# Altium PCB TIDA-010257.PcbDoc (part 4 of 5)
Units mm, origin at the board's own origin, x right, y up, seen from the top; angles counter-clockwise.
Board outline 250 x 270 mm, 2 copper layers (Top Layer, Bottom Layer), stack 1.575 mm thick; 458 components, 220 nets, 1154 pads, 1226 vias.
Unrouted connection lines stored in the file: 314.
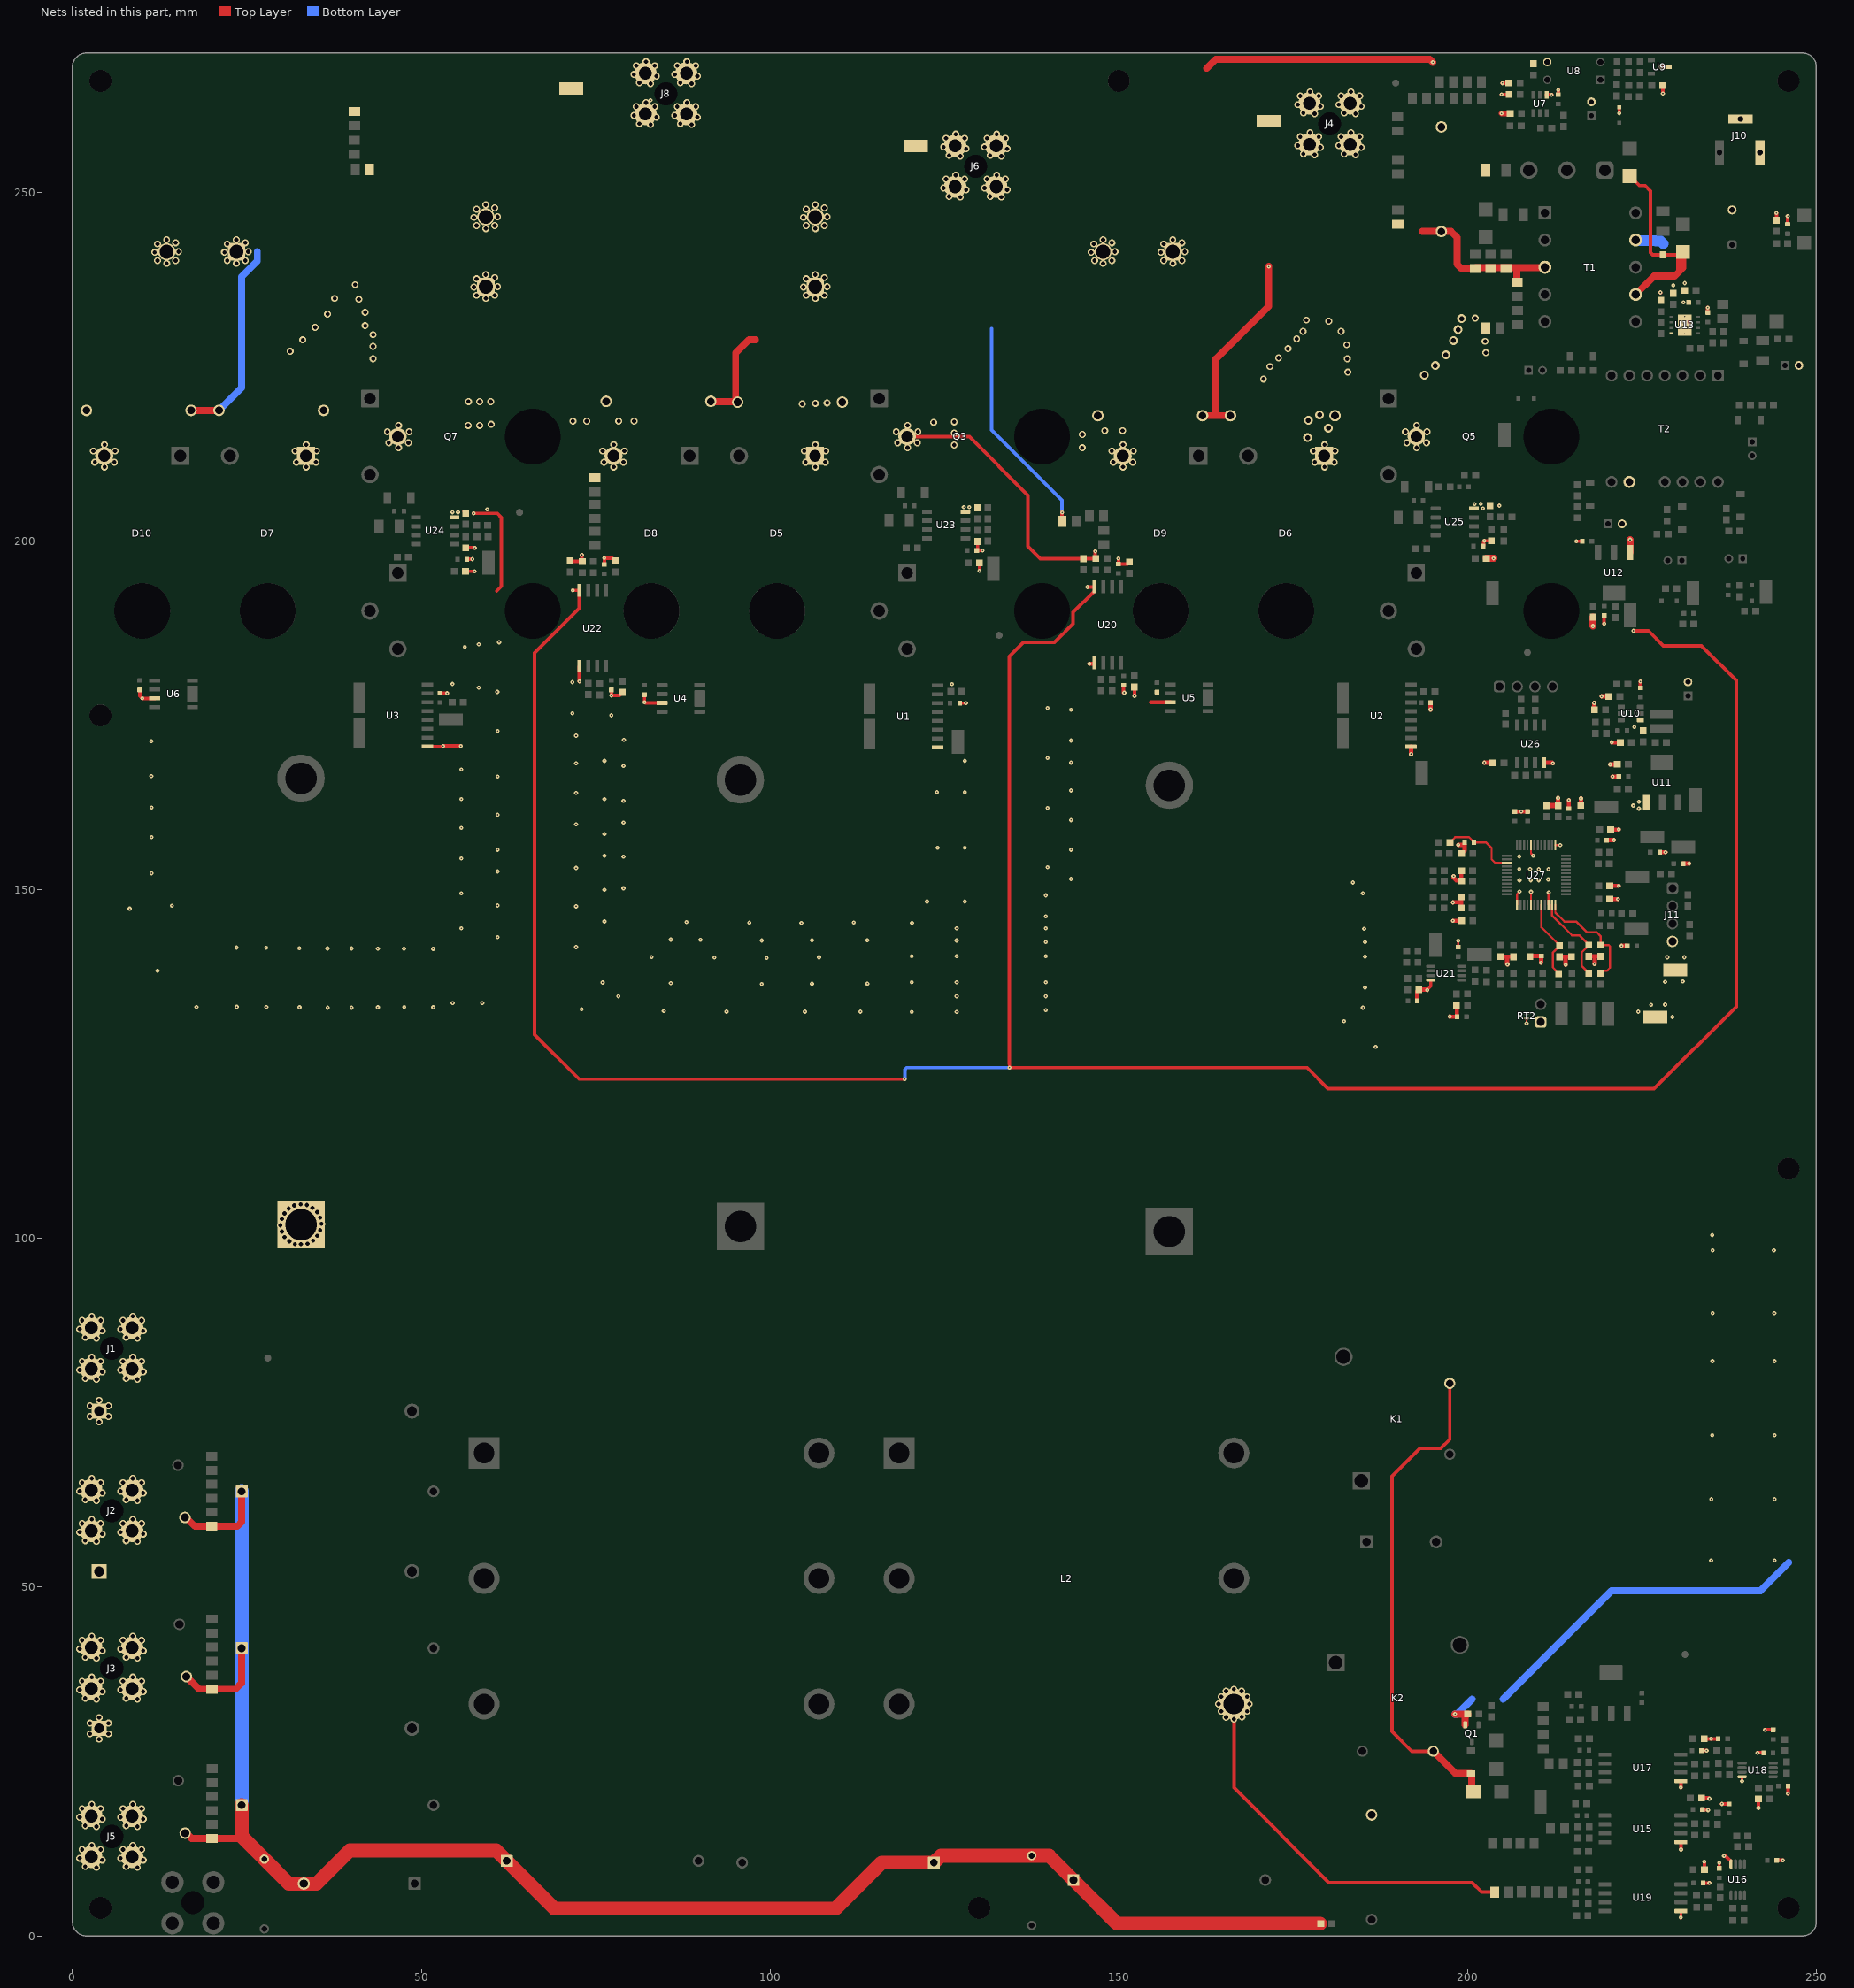
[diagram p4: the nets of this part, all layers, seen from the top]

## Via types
v1: diameter 1, hole 0.6, Top Layer to Bottom Layer, 760 vias
v2: diameter 0.6, hole 0.2, Top Layer to Bottom Layer, 452 vias
v3: diameter 1.27, hole 0.711, Top Layer to Bottom Layer, 10 vias
v4: diameter 0.5, hole 0.2, Top Layer to Bottom Layer, 4 vias

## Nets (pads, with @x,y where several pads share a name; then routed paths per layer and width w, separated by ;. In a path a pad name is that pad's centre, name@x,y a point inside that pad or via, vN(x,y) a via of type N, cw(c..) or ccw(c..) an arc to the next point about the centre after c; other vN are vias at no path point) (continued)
V_C: L2.6 L7.1 R104.1 | length 57.5
  Top Layer w0.2: L7.1@29.7,104.9 30.6,104.9 L7.1@30.7,104.8 ; L7.1@29.75,99.2 29.9,99.2 L7.1@30.4,98.7
  Top Layer w0.5: L2.6@166.5,33.25 v1(166.5,31.1) 166.5,21.25 180.113,7.637 200.65,7.637 202.015,6.271 R104.1@203.891,6.271
  other v1: 165.4,31.35 167.65,31.4 164.7,32.2 168.4,32.2 164.3,33.25 168.7,33.25 164.7,34.3 168.4,34.3 165.4,35.1 167.6,35.1 166.5,35.375 31.9,99.2 32.75,99.2 33.7,99.265 31.1,99.6 34.5,99.7 30.4,100.2 35.1,100.4 30,101 35.5,101.2 29.8,101.9 35.7,102.1 30,102.8 35.5,103 30.4,103.6 35.1,103.8 31,104.3 34.4,104.4 31.8,104.735 33.6,104.8 32.7,104.9
V_L1: F1.1 J1.1
  other v1: 3.83,73.7 2.52,74.468 5.16,74.468 2.52,76 5.16,76 3.83,76.8 3.43,79.817 9.3,79.817 1.83,79.93 7.7,79.93 4.267,80.88 10.137,80.88 1.03,81.13 6.9,81.13 1.38,82.38 4.03,82.38 7.25,82.38 9.9,82.38 2.77,82.967 8.64,82.967 3.43,85.687 9.3,85.687 1.83,85.8 7.7,85.8 4.267,86.75 10.137,86.75 1.03,87 6.9,87 1.38,88.25 4.03,88.25 7.25,88.25 9.9,88.25 2.77,88.837 8.64,88.837
V_L2: F2.1 J2.1
  other v1: 3.43,56.567 9.3,56.567 1.83,56.68 7.7,56.68 4.267,57.63 10.137,57.63 1.03,57.88 6.9,57.88 1.38,59.13 4.03,59.13 7.25,59.13 9.9,59.13 2.77,59.717 8.64,59.717 3.43,62.437 9.3,62.437 1.83,62.55 7.7,62.55 4.267,63.5 10.137,63.5 1.03,63.75 6.9,63.75 1.38,65 4.03,65 7.25,65 9.9,65 2.77,65.587 8.64,65.587
V_L3: F3.1 J3.1
  other v1: 3.83,28.2 2.52,28.968 5.16,28.968 2.52,30.5 5.16,30.5 3.83,31.3 3.43,33.952 9.3,33.952 1.83,34.065 7.7,34.065 4.267,35.015 10.137,35.015 1.03,35.265 6.9,35.265 1.38,36.515 4.03,36.515 7.25,36.515 9.9,36.515 2.77,37.103 8.64,37.103 3.43,39.822 9.3,39.822 1.83,39.935 7.7,39.935 4.267,40.885 10.137,40.885 1.03,41.135 6.9,41.135 1.38,42.385 4.03,42.385 7.25,42.385 9.9,42.385 2.77,42.973 8.64,42.973
V_Relay: D2.1 D4.1 K1.4 K2.4 | length 71.5
  Top Layer w0.5: K2.4@195.08,26.479 192,26.479 189.151,29.328 189.151,65.901 193.155,69.905 196.155,69.905 197.45,71.2 K1.4@197.45,79.22
  Top Layer w1: K2.4@195.08,26.479 198.264,23.294 D2.1@200.499,23.294 ; D2.1@200.609,23.252 200.609,20.951 D4.1@200.831,20.729
VA_AD: C85.2 R85.1 U27.20 | length 11.7
  Top Layer w0.3: U27.20@210.588,147.877 210.588,144.627 213.198,142.017 C85.2@213.198,141.992 213.198,141.967 212.449,141.218 212.44,141.218 212.213,140.991 212.213,138.896 213.088,138.021 R85.1@213.088,137.996
Vaux: C34.2 D11.2 D13.2 T1.7 | length 29.7
  Top Layer w0.5: D13.2@223.25,252.36 224.619,250.991 225.458,250.991 226.229,250.22 226.229,241.361 226.522,241.068 C34.2@228.058,241.068 D11.2@230.461,241.068
  Top Layer w1: T1.7@224.098,235.38 226.718,238 229.673,238 230.872,239.199 D11.2@230.872,241.48 ; 230.372,239.086 230.372,240.98 D11.2@230.461,241.068
VB_AD: C95.2 R98.1 U27.23 | length 13.6
  Top Layer w0.3: U27.23@212.088,147.877 212.088,146.362 214.963,143.487 216.007,143.487 217.391,142.103 C95.2@217.391,142.078 217.391,142.053 216.388,141.051 216.388,139.067 217.391,138.065 R98.1@217.391,138.04 R98.1@217.327,138.103
VBUSM: C10.2 C14.2 C15.2 C16.2 C18.1 C19.2 C22.1 C23.2 C24.1 C25.1 C27.1 C53.2 C54.2 C55.1 C56.1 C106.2 C107.1 C115.2 C116.1 J6.1 Q3.2 Q5.2 Q7.2 R17.1 R19.2 R117.2 R120.2 R128.1 R131.1 T2.9 TP4.1 U12.1 U20.4 U22.4 | length 516.7
  Top Layer w0.5: R131.1@71.315,197.167 71.37,197.112 73.019,197.112 R128.1@73.028,197.103 ; v2(71.736,192.946) 71.81,192.946 71.815,192.95 U22.4@72.66,192.95 72.66,190.367 66.25,183.957 66.25,129.25 72.65,122.85 v2(119.3,122.85) ; v2(73.028,198.038) R128.1@73.028,197.103 ; R128.1@73.074,197.057 R128.1@73.028,197.103 ; v2(76.236,197.57) v2@76.25,197.57 ; C116.1@76.25,196.675 v2@76.25,197.57 ; C115.2@77.815,197.166 77.815,197.191 77.59,197.416 77.565,197.416 77.412,197.57 v2@76.25,197.57 ; Q3.2@119.648,215 128.567,215 136.99,206.578 136.99,199.257 138.756,197.491 146.685,197.491 R117.2@146.7,197.506 146.636,197.57 v2(146.636,198.548) ; v2(145.499,193.42) 145.499,193.443 145.506,193.45 U20.4@146.518,193.45 146.518,192.85 143.45,189.782 143.45,188.175 142.377,187.102 cw(c139,190) 141.898,186.623 140.775,185.5 136.335,185.5 134.3,183.465 134.3,125.05 134.331,125.019 134.331,124.527 134.304,124.5 177,124.5 180,121.5 226.75,121.5 238.5,133.25 238.5,180.025 233.533,184.992 228.084,184.992 225.936,187.14 v2(223.775,187.14) ; v2(149.953,197.5) C107.1@149.953,196.718 151.229,196.718 151.5,196.989 C106.2@151.5,197.014 ; v2(215.597,199.993) C55.1@216.468,199.993 ; v2(219.578,188.159) C56.1@219.578,189.36
  Top Layer w1: C27.1@17,218.75 C23.2@21,218.75 ; C22.1@91.509,220.053 91.569,219.994 C19.2@95.071,219.994 ; C19.2@95.36,219.935 95.3,219.994 C19.2@95.071,219.994 ; 97.907,228.9 97,228.9 95.071,226.971 C19.2@95.071,219.994 ; C18.1@162,218 164,218 ; C14.2@166,218 164,218 ; v2(171.5,239.398) 171.5,233.7 163.935,226.135 163.935,218.065 164,218 ; v2(217.975,187.835) C53.2@217.975,189.11 ; U12.1@223.3,198.4 v2(223.3,200.197)
  Bottom Layer w0.5: v2(119.3,122.85) 119.305,122.855 119.305,124.207 119.598,124.5 v2(134.35,124.5)
  Bottom Layer w1: C23.2@21,218.75 24.25,222 24.25,237.925 26.5,240.175 26.5,241.5
  other v1: 46.745,213.4 119.698,213.4 192.698,213.4 126.4,213.78 45.345,214.1 48.145,214.1 118.298,214.1 121.098,214.1 191.298,214.1 194.098,214.1 126.4,215.504 45.145,215.7 48.245,215.7 118.098,215.7 121.198,215.7 191.098,215.7 194.198,215.7 46.745,216.6 56.723,216.6 58.365,216.6 119.698,216.6 192.698,216.6 60.02,216.75 123.434,217.043 126.4,217.105 58.365,219.999 59.942,219.999 56.764,220.021 202.622,227.024 202.516,228.657 201.098,231.972 23.5,239.821 157.75,239.821 22.181,240.252 24.781,240.252 156.431,240.252 159.031,240.252 21.79,241.421 156.04,241.421 25.19,241.507 159.44,241.507 22.181,242.62 156.431,242.62 24.781,242.792 159.031,242.792 23.49,243.221 157.74,243.221 59.25,244.821 106.5,244.821 57.931,245.252 60.531,245.252 105.181,245.252 107.781,245.252 57.54,246.421 104.79,246.421 60.94,246.507 108.19,246.507 57.931,247.62 105.181,247.62 60.531,247.792 107.781,247.792 59.24,248.221 106.49,248.221 127.283,249.339 133.153,249.339 125.683,249.452 131.553,249.452 128.12,250.402 133.99,250.402 124.883,250.652 130.753,250.652 125.233,251.902 127.883,251.902 131.103,251.902 133.753,251.902 126.623,252.489 132.493,252.489 127.283,255.209 133.153,255.209 125.683,255.322 131.553,255.322 128.12,256.272 133.99,256.272 124.883,256.522 130.753,256.522 125.233,257.772 127.883,257.772 131.103,257.772 133.753,257.772 126.623,258.359 132.493,258.359
  other v3: 193.804,223.809 195.381,225.191 196.905,226.71 197.974,228.78 198.639,230.33 199.155,231.922
VBUSN: C9.2 C12.2 C13.2 C17.2 C18.2 C20.2 C21.2 C22.2 C24.2 C25.2 C26.2 C27.2 C28.2 C29.2 C30.2 C31.1 C32.1 C33.1 C35.2 C36.1 C37.1 C40.1 C41.2 C43.2 C44.2 C45.1 C47.1 C48.2 C50.1 C51.2 C52.2 C61.2 C62.1 C71.1 C72.2 C81.1 C82.2 C84.1 C85.1 C86.1 C90.1 C91.2 C93.1 C94.1 C95.1 C96.1 C100.1 C101.2 C103.1 C104.1 C105.1 C109.1 C110.2 C112.1 C113.1 C114.2 C118.1 C119.2 C121.1 C122.1 C123.2 C124.1 C125.2 C128.2 C129.2 C130.1 C131.2 C132.1 C133.2 C136.2 C139.2 C140.2 C141.1 C143.1 C144.1 C145.1 C146.2 C147.1 C148.2 C149.1 C150.2 C151.2 C152.1 C153.1 C154.2 C155.1 C156.2 C157.1 D8.2 D9.2 D10.2 D14.2 J8.1 J10.2 J10.3 J11.4 J12.1 Q1.2 R2.2 R21.1 R28.1 R48.1 R49.1 R50.1 R55.1 R56.1 R76.1 R77.1 R102.1 R123.2 R125.1 R134.2 R151.2 R155.1 RT2.1 T1.9 TP6.1 TP24.1 TP25.1 U1.3 U2.3 U3.3 U4.3 U5.3 U6.3 U7.1 U8.3 U9.3 U10.1 U11.1 U13.8 U13.9@231.14,230.983 U15.5 U16.4 U17.5 U18.4 U19.5 U20.5 U21.4 U22.5 U23.4 U24.4 U25.4 U26.4 U27.13 U27.17 U27.22 U27.37 U27.44 | length 235.5
  Top Layer w0.3: C114.2@198.648,141.781 v2(198.648,142.715) ; U27.13@207.088,147.877 207.088,149.383 v2(207.456,149.752) ; v2(208.463,130.849) RT2.1@208.463,131.57 ; U27.17@209.088,147.877 v2(209.088,149.712) ; U27.44@209.088,156.377 209.088,155.227 v2(209.413,154.902) ; U27.22@211.588,147.877 211.588,149.569 v2(211.642,149.623) ; U27.37@212.588,156.377 212.588,156.393 v2(213.28,156.393)
  Top Layer w0.4: v2(194.222,135.631) 194.222,135.685 194.715,136.178 U21.4@194.715,137.069 ; v2(230.556,2.656) 230.556,2.544 230.577,2.524 U19.5@230.577,3.565 ; C105.1@236.076,9.684 v2(236.076,10.485) ; v2(239.357,22.191) U18.4@239.357,22.822
  Top Layer w0.5: C33.1@9.646,178.668 9.646,177.809 v2(9.997,177.458) U6.3@11.784,177.458 ; U3.3@50.875,170.555 v2@53.218,170.555 ; C26.2@52.683,178.215 53.673,178.215 53.713,178.175 v2(53.713,178.19) ; v2@53.177,170.595 53.177,170.615 53.198,170.635 v2(55.675,170.635) ; C139.2@56.125,204.29 56.35,204.065 C139.2@56.35,204.04 ; C129.2@56.35,195.675 v2(57.644,195.675) ; C133.2@56.374,199.043 57.644,199.043 v2(57.664,199.023) ; C130.1@56.525,197.402 56.532,197.409 57.302,197.409 v2(57.31,197.416) ; v2(57.498,203.988) 60.9,203.988 61.481,203.406 61.481,193.516 60.811,192.846 ; C119.2@77.25,178.671 v2(77.25,177.886) 78.396,177.886 78.565,178.055 78.59,178.055 78.815,178.28 C118.1@78.815,178.305 ; C31.1@82,177.984 v2(82,176.905) 82.027,176.905 82.126,176.806 U4.3@84.525,176.806 ; C13.2@127.175,176.78 127.18,176.774 128.094,176.774 v2(128.099,176.769) ; C124.1@129.638,198.668 129.644,198.662 130.451,198.662 v2(130.457,198.656) ; C125.2@129.75,199.95 129.766,199.934 129.766,198.689 C124.1@129.776,198.679 ; v2@130.027,195.777 C123.2@130.027,196.905 ; C110.2@150.69,179.32 150.69,178.234 150.695,178.229 150.732,178.266 v2(150.786,178.266) ; v2(152.25,177.819) C109.1@152.25,179.08 ; C132.1@202.214,199.292 202.289,199.367 202.289,199.915 202.389,200.015 v2(202.389,200.042) 202.404,200.057 C136.2@203.436,200.057 ; C140.2@203.209,205.103 C140.2@203.213,205.099 ; v2@204.545,205.088 v2(204.549,205.084) ; v2(204.861,264.062) C44.2@205.946,264.062 ; v2(204.986,265.691) R50.1@205.944,265.692 ; U7.1@211.336,264 211.348,264.012 v2(212.05,264.012) ; C40.1@213,264.05 v2(213,264.7) ; v2(221.75,261.372) D14.2@221.75,262.207 ; v2(227.637,235.667) v2@227.69,235.615 ; v2(227.637,268) 228.715,268 U9.3@228.734,267.98 ; R49.1@227.994,265.328 227.999,265.323 v2(227.999,264.2) ; U15.5@230.577,13.441 230.577,12.394 v2(230.6,12.369) v2(230.6,12.369) ; v2(230.577,21.281) U17.5@230.577,22.192 ; C91.2@233.518,26.566 v2(234.268,26.566) ; C81.1@233.545,19.787 234.551,19.787 v2(234.664,19.673) ; C82.2@233.675,18.096 233.7,18.071 234.443,18.071 v2(234.479,18.036) v2(234.479,18.036) ; C101.2@233.751,7.567 234.618,7.567 234.648,7.597 234.66,7.597 v2(234.664,7.593) ; C90.1@233.925,28.265 234.898,28.265 v2(234.904,28.26) 234.906,28.262 235.939,28.262 C96.1@235.942,28.265 ; v2(233.93,10.628) 233.926,10.623 233.926,10.621 233.941,10.607 C100.1@233.941,9.469 ; v2(234.424,233.488) 234.424,232.822 C62.1@234.453,232.792 ; v2(236.45,18.923) C86.1@237.509,18.923 ; v2(236.759,11.457) 236.778,11.438 237.016,11.438 U16.4@237.737,10.717 ; v2(241.566,26.25) C103.1@242.446,26.25 ; v2(241.692,18.336) R102.1@241.692,19.613 ; v2(242.626,29.547) 242.621,29.551 242.621,29.553 242.631,29.543 C93.1@243.816,29.543 ; v2(244.258,247.052) 244.284,247.026 R28.1@244.284,246.021 ; C84.1@244.324,10.832 v2(245.2,10.832) ; C36.1@245.885,245.425 245.885,246.62 v2(245.894,246.629) ; C94.1@245.925,21.5 245.925,20.346 245.933,20.354 v2(245.933,20.389)
  Top Layer w0.6: v2(72.66,179.905) U22.5@72.66,182.05 ; v2(145.772,182.414) 146.518,182.414 U20.5@146.518,182.55 ; 154.591,176.895 U5.3@157.4,176.895 ; v2(191.899,169.458) U2.3@191.899,170.512 ; C113.1@192.8,134.101 192.8,135.471 192.998,135.669 R123.2@192.998,135.694 194.159,135.694 v2(194.222,135.631) ; v2(194.701,175.852) 194.703,175.854 C20.2@194.703,176.862 ; v2(197.455,131.825) 197.479,131.825 197.504,131.8 C122.1@198.505,131.8 198.48,131.825 198.48,133.367 R134.2@198.391,133.457 ; v2(197.89,145.564) 197.904,145.578 C156.2@199.153,145.578 ; v2(197.904,148.184) 197.931,148.211 199.077,148.211 ; v2(198.001,151.968) 198.001,151.728 198.352,151.377 198.989,151.377 C21.2@199.114,151.252 C28.2@199.114,152.752 ; v2(198.673,156.455) 199.567,156.455 199.567,155.613 199.174,155.22 C29.2@199.149,155.22 ; C121.1@199.077,147.428 199.077,148.211 ; C112.1@199.077,148.995 199.077,148.211 ; v2(202.406,168.237) C141.1@203.637,168.237 ; C30.2@204.772,140.418 204.773,140.416 205.667,140.416 ; v2(205.724,139.303) 205.667,139.36 205.667,140.416 ; C12.2@206.563,140.415 206.561,140.416 205.667,140.416 ; C153.1@206.78,161.227 v2(207.699,161.227) C146.2@208.588,161.227 ; C154.2@208.963,140.418 209.063,140.518 C145.1@210.563,140.518 ; v2(210.527,139.54) 210.563,139.575 C145.1@210.563,140.518 ; C145.1@210.588,140.543 C145.1@210.563,140.518 ; U26.4@210.937,168.237 212.149,168.237 212.23,168.155 v2(212.241,168.155) ; R155.1@212.965,162.078 212.965,163.16 v2(212.973,163.168) ; C85.1@213.198,140.392 213.216,140.41 214.051,140.41 ; v2(214.062,139.259) 214.078,139.243 214.088,139.243 214.051,139.28 214.051,140.41 ; v2(214.517,162.862) 214.532,162.846 C148.2@214.532,161.663 ; C17.2@214.904,140.428 214.885,140.41 214.051,140.41 ; C147.1@216.248,162.138 v2(216.248,163.093) ; C95.1@217.391,140.478 218.23,140.478 ; v2(218.159,176.808) 218.159,175.852 R56.1@218.189,175.822 ; v2(218.21,139.36) 218.23,139.379 218.23,140.478 ; C104.1@219.069,140.478 218.23,140.478 ; v2(219.212,177.747) 220.234,177.747 R55.1@220.237,177.75 ; C152.1@219.938,157.127 v2(221,157.127) ; C151.2@220.392,148.684 221.558,148.684 v2(221.57,148.673) ; C150.2@220.405,150.559 v2(221.68,150.559) ; v2(220.456,168) C48.2@221.453,168 ; C155.1@220.534,158.638 221.67,158.638 v2(221.68,158.648) ; v2(220.658,171.152) 220.681,171.129 C52.2@221.901,171.129 ; v2(220.811,166.228) 220.77,166.228 220.792,166.25 C50.1@221.68,166.25 ; v2(222.072,141.967) C157.1@222.886,141.967 ; C47.1@224.776,178.984 224.783,178.991 v2(224.783,179.892) ; U11.1@225.496,162.634 U11.1@225.609,162.521 ; C144.1@227.54,155.402 v2(228.375,155.402) ; C143.1@230.901,153.766 v2(231.776,153.766)
  Top Layer w0.8: v2(204.861,261.344) C43.2@206.121,261.344 ; U8.3@211.332,268.706 U8.3@211.44,268.706 ; R151.2@211.348,162.078 R155.1@212.965,162.078 ; C61.2@247.5,225.22 C61.2@247.586,225.134
  Top Layer w1: 162.6,267.8 163.912,269.112 194.581,269.112 v2(195.016,268.677) ; v2(198.193,31.809) R2.2@200.038,31.809 199.662,31.433 Q1.2@199.662,30.26 ; C131.2@202.676,197.542 v2(203.746,197.542)
  Bottom Layer w1: v2(198.193,31.809) 198.51,31.809 200.645,33.944 ; 205.093,33.944 220.649,49.5 242,49.5 246.05,53.55
  Bottom Layer w1.5: T1.9@224.098,243.18 224.169,243.109 226.909,243.109 226.997,243.021 227.705,243.021 228.058,242.668
  other v1: 4.6,210.63 77.6,210.63 150.6,210.63 3.2,211.33 6,211.33 76.2,211.33 79,211.33 149.2,211.33 152,211.33 3,212.93 6.1,212.93 76,212.93 79.1,212.93 149,212.93 152.1,212.93 144.751,213.389 4.6,213.83 77.6,213.83 150.6,213.83 144.77,215.31 147.983,215.845 150.55,215.845 71.736,217.2 73.724,217.2 78.313,217.2 80.5,217.2 13.5,239.821 147.75,239.821 12.181,240.252 14.781,240.252 146.521,240.252 149,240.252 11.79,241.421 146.04,241.421 15.19,241.507 149.44,241.507 12.181,242.62 146.431,242.62 14.781,242.792 149,242.792 13.49,243.221 147.74,243.221 82.871,259.747 88.741,259.747 81.271,259.86 87.141,259.86 83.708,260.81 89.578,260.81 80.471,261.06 86.341,261.06 80.821,262.31 83.471,262.31 86.691,262.31 89.341,262.31 82.211,262.898 88.081,262.898 82.871,265.617 88.741,265.617 81.271,265.73 87.141,265.73 83.708,266.68 89.578,266.68 80.471,266.93 86.341,266.93 80.821,268.18 83.471,268.18 86.691,268.18 89.341,268.18 82.211,268.768 88.081,268.768
  other v2: 234.92,53.822 244,53.833 234.941,62.62 244,62.62 235.057,71.781 244,71.781 235.112,82.4 244,82.4 235.124,89.3 243.982,89.3 235.121,98.3 243.908,98.3 235.066,100.5 186.813,127.5 182.3,131.178 229.364,131.77 120.307,132.5 126.75,132.5 93.772,132.535 105,132.535 112.947,132.535 224.466,132.526 84.772,132.604 139.55,132.75 73,132.883 185,133.094 36.569,133.111 40.022,133.111 32.543,133.146 43.772,133.146 51.718,133.146 17.772,133.181 27.793,133.181 47.543,133.181 23.543,133.215 226.32,133.515 228.327,133.541 54.5,133.758 58.75,133.758 78.25,134.75 126.75,134.75 139.55,134.75 185.293,135.975 98.797,136.5 106,136.535 113.947,136.535 85.772,136.604 76,136.71 120.307,136.75 126.75,136.75 139.55,136.75 228.327,136.792 230.845,136.856 12.2,138.4 99.5,140.25 92.022,140.285 107.022,140.319 228.633,140.328 231.059,140.328 83.022,140.354 185.293,140.431 120.307,140.5 126.75,140.5 139.55,140.5 51.697,141.542 43.772,141.577 47.522,141.577 36.547,141.611 40.022,141.611 32.522,141.646 27.772,141.681 23.522,141.715 72.2,141.8 139.55,142.5 185.293,142.501 98.797,142.75 126.75,142.75 106,142.785 113.947,142.785 90.022,142.819 85.772,142.854 60.926,143.217 185.188,144.416 55.743,144.495 126.75,144.5 139.55,144.5 104.5,145.255 120.356,145.255 97.022,145.289 112.022,145.324 88.022,145.359 76.25,145.467 139.55,146.195 8.2,147.3 72.2,147.631 14.243,147.715 60.926,147.75 122.5,148.335 127.915,148.335 139.55,149.2 55.743,149.5 185,149.502 76.25,150 79,150.217 183.546,151.059 207.43,151.377 209.063,151.377 210.213,151.377 211.559,151.494 143.163,151.556 11.343,152.378 60.926,152.642 208.97,152.971 210.213,152.952 211.602,152.952 207.421,152.989 72.2,153.131 139.8,153.25 55.743,154.5 79,154.75 207.421,154.783 76.25,154.892 60.926,155.75 143.163,155.75 124.02,156.022 127.915,156.022 11.322,157.55 76.25,158 55.743,158.872 72.2,159.381 79,159.642 143.163,160 60.926,160.75 224.566,161.65 139.8,161.75 11.322,161.8 223.761,162.076 224.559,162.634 79,162.75 55.743,163 76.25,163 72.2,163.881 123.939,164 127.915,164 143.163,164.25 60.926,166.25 11.3,166.3 55.743,167.25 79,167.75 72.2,168.131 143.163,168.25 76.25,168.5 127.915,168.5 139.8,168.902 53.152,170.635 11.3,171.3 143.163,171.402 79.051,171.5 72.2,172.107 60.926,172.782 223.916,173.352 77.25,175.032 71.65,175.323 143.163,175.814 139.8,176.07 60.902,178.39 58.247,179 126.101,179.502 54.454,179.519 71.65,179.79 56.245,184.814 58.247,185.213 61.164,185.5 130.027,195.75 54.454,204.158 55.262,204.158 59.461,204.569 202.211,204.667 127.781,204.887 128.551,204.878 201.012,205.327 201.876,205.337 230.957,234.238 229.477,236.68 231.14,237 82.861,263.25
  other v4: 231.14,229.733 230.4,230.983 231.88,230.983 231.14,232.233
VBUSP: C14.1 C15.1 C16.1 C19.1 C23.1 C37.2 C38.1 D5.1 D6.1 D7.1 J4.1 R14.2 R27.2 R30.2 R31.2 R114.1 T1.3 TP2.1 | length 56.1
  Top Layer w0.5: R114.1@141.875,202.837 v2(141.875,204.125)
  Top Layer w1: 193.514,244.407 C37.2@196.25,244.407 197.642,244.407 198.488,243.562 198.488,239.711 199.074,239.125 R30.2@201.113,239.125 201.19,239.203 C38.1@205.521,239.203 ; C38.1@205.531,239.193 C38.1@205.521,239.203 ; R14.2@207.073,237.137 207.073,239.106 207.17,239.203 ; T1.3@211.098,239.28 211.021,239.203 207.17,239.203 ; C38.1@205.521,239.203 207.17,239.203
  Bottom Layer w0.5: 131.75,230.5 131.75,215.957 141.875,205.832 v2(141.875,204.125)
  other v1: 33.5,210.63 106.5,210.63 179.5,210.63 32.1,211.33 34.9,211.33 105.1,211.33 107.9,211.33 178.1,211.33 180.9,211.33 31.9,212.93 35,212.93 104.9,212.93 108,212.93 177.9,212.93 181,212.93 33.5,213.83 106.5,213.83 179.5,213.83 104.604,219.685 106.5,219.774 108.19,219.833 170.75,223.262 182.834,224.234 171.662,225.049 182.75,226.135 43.1,226.162 172.9,226.288 31.2,227.213 174.243,227.6 43.093,227.919 182.677,228.157 33.011,228.868 175.5,229 43.1,229.617 176.4,230.1 181.862,230.1 34.794,230.655 41.955,230.896 180.1,231.548 176.9,231.7 36.567,232.55 41.955,232.819 41.047,234.682 37.582,234.821 59.25,234.821 106.5,234.821 57.931,235.252 60.531,235.252 105.181,235.252 107.781,235.252 57.54,236.421 104.79,236.421 60.94,236.507 108.19,236.507 40.518,236.783 57.931,237.62 105.181,237.62 60.531,237.792 107.781,237.792 59.24,238.221 106.49,238.221 178.063,255.417 183.933,255.417 176.463,255.53 182.333,255.53 178.9,256.48 184.77,256.48 175.663,256.73 181.533,256.73 176.013,257.98 178.663,257.98 181.883,257.98 184.533,257.98 177.403,258.567 183.273,258.567 178.063,261.287 183.933,261.287 176.463,261.4 182.333,261.4 178.9,262.35 184.77,262.35 175.663,262.6 181.533,262.6 176.013,263.85 178.663,263.85 181.883,263.85 184.533,263.85 177.403,264.437 183.273,264.437
  other v3: 177.084,214.847 180.064,216.228 177.164,217.309 178.796,218.124
VC_AD: C104.2 R109.1 U27.24 | length 16.5
  Top Layer w0.3: U27.24@212.588,147.877 212.588,146.744 213.877,145.455 215.55,145.455 217.069,143.935 218.514,143.935 219.069,143.38 C104.2@219.069,142.078 220.238,142.078 220.413,141.903 220.413,138.829 219.975,138.39 219.394,138.39 219.069,138.065 R109.1@219.069,138.04
VN: C1.1 C2.1 C3.1 C4.1 C5.1 C6.1 C7.1 C8.1 GD1.2 J5.1 R9.1 R10.1 R11.1 R12.2 RV1.1 RV2.1 RV3.1 | length 255.8
  Top Layer w1: RV1.1@16.117,60 16.293,60 17.559,58.734 R9.1@19.95,58.734 23.623,58.734 24.25,59.361 C3.1@24.25,63.75 ; RV2.1@16.15,14.75 16.326,14.75 17.092,13.984 R11.1@19.991,13.984 24.516,13.984 ; RV3.1@16.325,37.187 18.144,35.368 R10.1@19.991,35.368 23.369,35.368 24.25,36.249 C2.1@24.25,41.25 ; RV3.1@16.449,37.187 RV3.1@16.625,37.187 ; R12.2@178.85,1.75 R12.2@178.95,1.75
  Top Layer w2: C1.1@24.25,18.75 24.25,14.25 24.516,13.984 C8.1@27.5,11 31,7.5 GD1.2@33.154,7.5 35,7.5 39.75,12.25 60.75,12.25 C5.1@62.25,10.75 69.1,3.9 109.4,3.9 116,10.5 C4.1@123.5,10.5 124.5,11.5 C7.1@137.5,11.5 140,11.5 C6.1@143.5,8 149.75,1.75 R12.2@178.85,1.75
  Bottom Layer w2: C1.1@24.25,18.75 C2.1@24.25,41.25 C3.1@24.25,63.75
  other v1: 3.43,9.817 9.3,9.817 1.83,9.93 7.7,9.93 4.267,10.88 10.137,10.88 1.03,11.13 6.9,11.13 1.38,12.38 4.03,12.38 7.25,12.38 9.9,12.38 2.77,12.967 8.64,12.967 3.43,15.687 9.3,15.687 1.83,15.8 7.7,15.8 4.267,16.75 10.137,16.75 1.03,17 6.9,17 1.38,18.25 4.03,18.25 7.25,18.25 9.9,18.25 2.77,18.837 8.64,18.837
XRSn: C149.2 R154.2 U27.3 | length 10.9
  Top Layer w0.3: R154.2@197.479,156.812 197.504,156.812 198.232,157.54 200.214,157.54 200.917,156.837 C149.2@200.917,156.812 202.624,156.812 203.454,155.982 203.454,154.377 203.954,153.877 U27.3@205.588,153.877
pads on no net: D5. D6. D7. D8. D9. D10. FID1.1 FID2.1 FID3.1 FID4.1 FID5.1 FID6.1 J1. J2. J3. J4. J5. J6. J7. J8. MP1. MP2. MP3. MP4. MP5. MP6. MP7. MP8. Q2. Q3. Q4. Q5. Q6. Q7. RT2.1S RT2.2S T1.2 T1.4 T1.5 T1.6 T1.8 T1.10 T2.2 U1.4 U1.5 U1.7 U1.9 U1.10 U2.4 U2.5 U2.7 U2.9 U2.10 U3.4 U3.5 U3.7 U3.9 U3.10 U4.2 U5.2 U6.2 U13.9@231.14,230.228 U13.9@231.14,231.738 U27.4 U27.7 U27.10 U27.16 U27.29 U27.31 U27.41 U27.42 U27.47

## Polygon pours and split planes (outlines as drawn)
NetC54_1 on Top Layer "BOTTOM_LAYER_NONET_P-001" (solid, pour order 213): 19 vertices, not listed, extent 214.631,197.32 221.294,205.859
VBUSN on Top Layer "Top Layer-VBUSN 2" (solid, remove dead copper, pour order 212): 23 vertices, not listed, extent 7.7,132.449 61.318,180.021
VBUSN on Top Layer "BOTTOM_LAYER_NONET_P-001" (solid, pour order 211): 211.827,269.627 212.25,269.204 212.25,268.179 211.997,267.926 194.667,267.926 193.75,268.843 193.75,269.111 194.266,269.627
VBUSN on Top Layer "Top Layer-VBUSN" (solid, remove dead copper, pour order 208): 52 vertices, not listed, extent 0.75,205 196.051,269.409
VBUSN on Top Layer "Top Layer-VBUSN 3" (solid, pour order 210): 21 vertices, not listed, extent 138.451,126.691 187.305,180.68
VBUSP on Top Layer "Top Layer-VBUSP" (solid, remove dead copper, pour order 206): 35 vertices, not listed, extent 167.576,208.807 195.241,265.314
VBUSM on Top Layer "Top Layer-VBUSM" (solid, pour order 202): 21 vertices, not listed, extent 41.955,212.23 72.292,256.992
VBUSP on Top Layer "Top Layer-VBUSP 1" (solid, pour order 200): 25 vertices, not listed, extent 29.5,208.5 44.053,238.337
VBUSM on Top Layer "Top Layer-VBUSM 2" (solid, pour order 198): 117.293,213.057 118.12,212.23 130.614,212.23 134.5,216.116 134.5,257.641 132.82,259.321 103.621,259.321 91.75,247.45 91.75,231.892 97.142,226.5 117,226.5 119.3,224.2 119.3,219.05 117.293,217.043
VBUSM on Top Layer "Top Layer-VBUSM 1" (solid, pour order 189): 201.113,221.205 203.327,223.419 203.327,227.024 203.327,232.105 202.793,232.639 198.782,232.639 192.431,226.288 192.431,218.888 190.25,216.706 190.25,213.716 191.493,212.473 199.155,212.473 201.113,214.431 201.113,220.357
GND_GATEB on Top Layer "Top Layer-GND_GATEB" (solid, pour order 187): 17 vertices, not listed, extent 190.625,182.297 197.145,201.188
QB_GATE on Top Layer "BOTTOM_LAYER_NONET_P-001" (solid, pour order 186): 186,205.14 186,199.04 190.837,194.203 193.754,194.203 193.848,194.297 193.848,196.187 193.135,196.9 193.135,200.689 190.75,203.074 190.75,204.752 189.64,205.863 189.64,207.581 189.321,207.9 186.3,207.9 186,207.6
QA_GATE on Top Layer "BOTTOM_LAYER_NONET_P-001" (solid, pour order 185): 17 vertices, not listed, extent 113,194.203 120.848,207.9
QC_GATE on Top Layer "BOTTOM_LAYER_NONET_P-001" (solid, pour order 184): 18 vertices, not listed, extent 40,194.203 47.848,207.9
3.3V_ACSensing on Top Layer "BOTTOM_LAYER_NONET_P-001" (solid, pour order 181): 208.728,19.023 207.325,17.62 207.325,16.987 207.632,16.68 213.9,16.68 214.146,16.927 214.146,23.029 213.713,23.462 209.004,23.462 208.728,23.186
NetC74_1 on Top Layer "BOTTOM_LAYER_NONET_P-001" (solid, pour order 180): 25 vertices, not listed, extent 215.47,29.684 224.5,38.883
15V on Top Layer "BOTTOM_LAYER_NONET_P-001" (solid, pour order 179): 24 vertices, not listed, extent 239.037,222.477 249.8,244.075
VBUSN on Top Layer "BOTTOM_LAYER_NONET_P-001" (solid, pour order 178): 195.016,253.689 196.598,252.107 202.955,252.107 203.192,252.344 203.192,259.035 201.227,261 195.466,261 195.016,260.55
VBUSN on Top Layer "BOTTOM_LAYER_NONET_P-001" (solid, pour order 177): 28 vertices, not listed, extent 226.641,228.833 232.109,237.5
NetD20_2 on Top Layer "BOTTOM_LAYER_NONET_P-001" (solid, pour order 176): 20 vertices, not listed, extent 230.168,222.565 234.187,230.097
NetC4_2 on Top Layer "Top Layer-NetC4_2" (solid, pour order 174): 84,55.8 84,44.6 85.1,43.5 120.125,43.5 122,45.375 122,55.25 119.75,57.5 85.7,57.5
NetC5_2 on Top Layer "Top Layer-NetC5_2" (solid, pour order 172): 119.75,61.5 122,63.75 122,71.5 119.5,74 93.75,74 77.1,74 75.6,72.5 75.6,62.3 76.4,61.5 91.4,61.5
NetR40_1 on Top Layer "BOTTOM_LAYER_NONET_P-001" (solid, pour order 168): 211.037,261.766 211.037,260.671 211.158,260.55 214.383,260.55 214.443,260.61 214.443,261.766 214.209,262 211.159,262 211.032,261.873
NetR15_2 on Top Layer "BOTTOM_LAYER_NONET_P-001" (solid, pour order 167): 191.291,168.5 191.298,168.493 191.298,164.047 193.051,162.294 194.655,162.294 196.048,163.687 196.048,167.876 194.555,169.369 192.136,169.369 191.292,168.525
VBUSN on Top Layer "BOTTOM_LAYER_NONET_P-001" (solid, remove dead copper, pour order 165): 227.098,250.902 230.829,247.171 233.389,247.171 236.144,244.417 242.59,244.417 243.248,245.074 249.427,245.074 249.724,245.371 249.724,267.945 248.041,269.627 227.854,269.627 227.098,268.87
NetC68_2 on Top Layer "BOTTOM_LAYER_NONET_P-001" (solid, pour order 164): 203.963,219.474 203.963,214.544 202.544,213.125 202.544,211.69 206.499,211.69 206.799,211.991 206.799,216.276 208.975,218.452 208.975,219.249 208.75,219.474 205.591,219.474
PWMB on Top Layer "BOTTOM_LAYER_NONET_P-001" (solid, pour order 163): 201.965,188.921 202.45,188.437 204.41,188.437 205.136,189.162 205.136,195.959 204.649,196.445 202.377,196.445 201.965,196.033
NetC64_2 on Top Layer "BOTTOM_LAYER_NONET_P-001" (solid, pour order 162): 23 vertices, not listed, extent 236.621,190.549 243.771,204.024
NetC53_1 on Top Layer "BOTTOM_LAYER_NONET_P-001" (solid, pour order 161): 21 vertices, not listed, extent 217.284,190.147 224.708,199.69
NetQ8_3 on Top Layer "BOTTOM_LAYER_NONET_P-001" (solid, pour order 159): 204.669,252.408 205.194,251.884 209.672,251.884 210.153,252.364 210.153,257.019 209.219,257.953 204.779,257.953 204.669,257.843
EGND on Top Layer "BOTTOM_LAYER_NONET_P-001" (solid, pour order 131): 11.65,1.25 12.9,0 23.25,0 24.5,1.25 24.5,7.9 22.47,9.93 13.573,9.93 11.65,8.007
VBUSN on Top Layer "Top Layer-VBUSN 1" (solid, remove dead copper, pour order 129): 27 vertices, not listed, extent 71.3,130 128.75,180.77
VBUSN on Top Layer "BOTTOM_LAYER_NONET_P-001" (solid, pour order 127): 227.242,142.095 227.242,136.675 227.477,136.44 232.267,136.44 232.791,136.964 232.791,142.463 231.875,143.38 228.342,143.38
VBUSN on Top Layer "BOTTOM_LAYER_NONET_P-001" (solid, pour order 126): 223.909,133.858 223.909,129.826 224.545,129.191 229.938,129.191 231.752,131.004 231.752,133.926 231.715,133.926 230.779,134.863 224.771,134.863
VBUSN on Top Layer "BOTTOM_LAYER_NONET_P-001" (solid, pour order 122): 206.578,154.807 206.58,154.804 206.58,149.215 207.012,148.783 212.838,148.783 213.163,149.107 213.163,153.481 212.768,153.877 208.765,153.877 208.272,154.37 208.272,155.072 208.073,155.27 207.088,155.27
VBUSN on Top Layer "BOTTOM_LAYER_NONET_P-001" (solid, pour order 121): 234.427,100.9 234.427,42.614 236.368,40.673 241.886,40.673 245.5,44.287 245.5,98.7 237.525,106.675 235.404,106.675 234.429,105.7
QA_C on Top Layer "Top Layer-QA_C" (solid, pour order 120): 25 vertices, not listed, extent 81.5,175.25 117.82,215.75
VBUSP on Top Layer "BOTTOM_LAYER_NONET_P-001" (solid, pour order 118): 102.75,210.25 104.703,208.297 108.608,208.297 110.762,210.45 110.762,220.138 110.156,220.744 103.867,220.744 102.75,219.627
V_C on Top Layer "TOP_LAYER_V_C_P028" (solid, pour order 28): 25 vertices, not listed, extent 21.5,25.7 170,126.75
QC_C on Top Layer "TOP_LAYER_QC_C_P001" (solid, pour order 1): 27 vertices, not listed, extent 0.75,175.25 44.932,215.75
QB_C on Top Layer "TOP_LAYER_QB_C_P017" (solid, pour order 17): 25 vertices, not listed, extent 154.5,175.25 190.837,215.75
GND_GATEA on Top Layer "Top Layer-GND_GATEA" (solid, pour order 105): 117.675,183.373 118.633,182.414 121.316,182.414 123.243,184.342 123.243,199.019 123.111,199.151 123.111,199.802 122.993,199.919 121.529,199.919 120.552,198.943 120.552,194.785 119.243,193.476 119.243,187.068 117.675,185.5
GND_GATEC on Top Layer "Top Layer-GND_GATEC" (solid, pour order 104): 44.559,183.512 45.821,182.25 48.151,182.25 50.243,184.342 50.243,199.019 50.111,199.151 50.111,199.802 49.993,199.919 48.529,199.919 47.552,198.943 47.552,194.785 46.243,193.476 46.243,187.068 44.559,185.384
VBUSN on Top Layer "BOTTOM_LAYER_NONET_P-001" (solid, pour order 102): 222.921,163.571 222.797,163.447 222.797,161.93 224.021,160.706 225.8,160.706 226.071,160.978 226.071,163.571
3.3V on Top Layer "BOTTOM_LAYER_NONET_P-001" (solid, pour order 101): 39 vertices, not listed, extent 209.338,155.402 234.353,167.271
GND_GATEA on Top Layer "BOTTOM_LAYER_NONET_P-001" (solid, pour order 96): 121.78,200.738 120.803,199.762 120.803,196.657 121.315,196.145 121.315,194.528 121.782,194.061 122.849,194.061 123.362,194.574 123.362,198.529 123.362,200.621 123.244,200.738
VBUSN on Top Layer "BOTTOM_LAYER_NONET_P-001" (solid, pour order 95): 53.867,205.124 54.328,205.584 60.194,205.584 60.827,204.95 60.827,203.415 60.487,203.076 53.985,203.076 53.867,203.193
VBUSN on Top Layer "BOTTOM_LAYER_NONET_P-001" (solid, pour order 93): 127.157,203.853 127.139,203.871 127.139,205.767 127.689,206.316 129.865,206.316 130.234,205.948 130.234,204.3 129.787,203.853 127.285,203.853
3.3V on Top Layer "BOTTOM_LAYER_NONET_P-001" (solid, pour order 91): 53.796,199.668 53.774,199.647 53.774,195.146 54.803,194.117 55.328,194.117 55.595,194.384 55.595,199.618 55.262,199.952 54.079,199.952
3.3V on Top Layer "BOTTOM_LAYER_NONET_P-001" (solid, pour order 90): 127.167,200.649 127.146,200.628 127.146,196.127 128.175,195.098 128.7,195.098 128.967,195.365 128.967,200.6 128.799,200.767 127.285,200.767
15V_GateC on Top Layer "BOTTOM_LAYER_NONET_P-001" (solid, pour order 89): 47.135,209.191 47.385,209.441 49.139,209.441 50.215,208.365 50.215,204.97 50.215,203.374 49.876,203.035 47.944,203.035 47.135,203.844 47.135,204.274
15V_GateA on Top Layer "BOTTOM_LAYER_NONET_P-001" (solid, pour order 88): 120.386,208.078 120.747,208.439 123.134,208.439 123.362,208.211 123.362,205.685 123.362,204.089 123.127,203.853 121.195,203.853 120.386,204.663 120.386,205.093
3.3V on Top Layer "BOTTOM_LAYER_NONET_P-001" (solid, pour order 87): 199.84,201.07 199.818,201.049 199.818,196.548 200.847,195.519 201.372,195.519 201.639,195.786 201.639,201.021 201.472,201.188 199.958,201.188
VBUSN on Top Layer "BOTTOM_LAYER_NONET_P-001" (solid, pour order 86): 199.84,204.715 201.263,206.138 205.855,206.138 206.799,205.194 206.799,204.643 206.46,204.303 199.958,204.303 199.84,204.421
15V_GateB on Top Layer "BOTTOM_LAYER_NONET_P-001" (solid, pour order 84): 193.307,208.528 193.668,208.889 196.055,208.889 196.387,208.557 196.387,206.239 196.283,206.135 196.283,204.538 196.048,204.303 194.116,204.303 193.307,205.112 193.307,205.542
5.4V on Top Layer "BOTTOM_LAYER_NONET_P-001" (solid, pour order 83): 229.76,163.571 229.76,161.361 230.24,160.88 233.846,160.88 234.122,161.157 234.122,172.693 233.056,173.759 226.234,173.759 226.19,173.715 226.19,172.609 226.363,172.437 230.34,172.437 230.733,172.044 230.733,164.544
NetC48_1 on Top Layer "BOTTOM_LAYER_NONET_P-001" (solid, pour order 82): 20 vertices, not listed, extent 222.553,161.342 230.401,171.795
15V on Top Layer "BOTTOM_LAYER_NONET_P-001" (solid, pour order 80): 225.142,177.925 225.609,178.392 225.609,180.424 225.969,180.784 232.452,180.784 233.179,180.058 233.179,177.026 232.236,176.083 224.711,176.083 224.421,176.373 224.421,177.925
VBUSN on Top Layer "BOTTOM_LAYER_NONET_P-001" (solid, pour order 81): 223.977,174.597 225.361,174.597 225.842,174.115 225.842,172.487 225.604,172.25 223.827,172.25 223.544,172.532 223.544,174.164
VN on Top Layer "TOP_LAYER_VN_P079" (solid, remove dead copper, pour order 79): 0.482,19.5 0.482,8.509 0.991,8 8.75,8 13.25,12.5 17.205,12.5 17.825,13.12 17.825,16.55 16.458,17.917 12.33,17.917 9.747,20.5 1.591,20.5 1.107,20.016
V_L3 on Top Layer "TOP_LAYER_V_L3_P078" (solid, pour order 78): 0.482,42.75 0.482,25.018 1.5,24 10.161,24 13.5,27.339 13.5,41.732 11.232,44 1.733,44
V_L2 on Top Layer "TOP_LAYER_V_L2_P077" (solid, pour order 77): 0.482,65.5 0.482,48.751 1.046,48.187 11.804,48.187 13.617,50 13.617,63.738 10.637,66.718 1.707,66.718
NetC2_2 on Top Layer "TOP_LAYER_NETC2_2_P076" (solid, pour order 76): 30.503,56.257 30.503,41.832 32.335,40 68.75,40 71,42.25 71,56 69,58 32.489,58
NetC1_2 on Top Layer "TOP_LAYER_NETC1_2_P075" (solid, pour order 75): 30.503,18.666 32.419,16.75 66.25,16.75 70,20.5 70,33.25 67.25,36 32.003,36 30.503,34.5
NetC3_2 on Top Layer "TOP_LAYER_NETC3_2_P074" (solid, pour order 74): 30,79.5 30,63.55 31.55,62 66.25,62 69.5,65.25 69.5,73.25 61.507,81.243 31.743,81.243
V_L1 on Top Layer "TOP_LAYER_V_L1_P073" (solid, pour order 73): 0.75,72.565 1.707,71.607 20.857,71.607 22.5,73.25 22.5,81.602 16.5,87.602 16.5,98.5 12.75,102.25 1.75,102.25 0.75,101.25 0.75,96
NetC6_2 on Top Layer "TOP_LAYER_NETC6_2_P072" (solid, pour order 72): 92.5,36.5 95.5,39.5 119.75,39.5 122,37.25 122,20.187 120.562,18.75 98.321,18.75 92.5,24.571
NetC59_2 on Top Layer "TOP_LAYER_NETC59_2_P067" (solid, pour order 67): 22 vertices, not listed, extent 228.31,187.597 233.611,202.361
V_B on Top Layer "TOP_LAYER_V_B_P023" (solid, pour order 23): 19 vertices, not listed, extent 151.25,38.016 229,109.7
VBUSN on Top Layer "TOP_LAYER_VBUSN_P038" (solid, pour order 38): 55.743,184.415 60.826,184.415 61.623,185.213 61.623,199.234 61.32,199.538 56.329,199.538 55.743,198.952
V_A on Top Layer "TOP_LAYER_V_A_P026" (solid, pour order 26): 85.5,111 85.5,101 92.5,94 129.75,94 147.25,76.5 183.53,76.5 188.069,81.039 188.069,85.931 184.25,89.75 154,89.75 146,97.75 146,107 140.25,112.75 87.25,112.75 86.25,111.75
NetK2_1 on Top Layer "TOP_LAYER_NETK2_1_P025" (solid, pour order 25): 161.75,57.75 161.75,49.25 163.5,47.5 170.778,47.5 177.5,40.778 177.5,35.25 178.806,33.944 184.334,33.944 186.5,36.11 186.5,51.75 186.75,52 186.75,58.049 186.049,58.75 162.75,58.75
NetK1_1 on Top Layer "TOP_LAYER_NETK1_1_P027" (solid, pour order 27): 159.25,72 159.25,64.75 161.25,62.75 186.75,62.75 187.75,63.75 187.75,71.5 184.75,74.5 161.75,74.5 160.75,73.5
V_B2 on Top Layer "Top Layer-NetL4_2" (solid, pour order 18): 151.5,157.5 154.456,154.544 177.508,154.544 183.047,160.083 183.047,165.153 183.047,174.322 182.868,174.5 163.454,174.5 160.45,171.496 153.475,171.496 151.5,169.521 151.5,160
NetL4_2 on Top Layer "Top Layer-NetL4_2" (solid, pour order 16): 86,154 89.195,150.805 113.305,150.805 115.75,153.25 115.75,167.74 115.435,168.055 115.19,168.3 115.19,174.265 114.954,174.5 90.229,174.5 87.975,172.246 86,170.271 86,160.75
NetL7_2 on Top Layer "TOP_LAYER_NETL7_2_P002" (solid, pour order 2): 41.722,174.75 29.103,174.75 17.65,174.75 16.4,173.5 16.4,156.35 23.75,149 45.5,149 50.136,153.636 50.136,165.519 48.655,167 43.225,167 42.085,168.14 42.085,174.389
VBUSP on Bottom Layer "BOTTOM_LAYER_NONET_P-001" (solid, pour order 205): 174.5,264.3 174.196,263.996 174.196,255.611 175.553,254.254 184.44,254.254 186.174,255.988 186.174,264.644 185.504,265.314 175.589,265.314 174.783,264.508
VBUSN on Bottom Layer "BOTTOM_LAYER_NONET_P-001" (solid, pour order 113): 17 vertices, not listed, extent 0.75,205.235 92.565,269.358
VBUSM on Bottom Layer "Bottom Layer-VBUSM" (solid, remove dead copper, pour order 196): 45 vertices, not listed, extent -4749.013,212.473 205.591,269.149
VBUSN on Bottom Layer "BOTTOM_LAYER_NONET_P-001" (solid, pour order 132): 145.284,242.589 145.321,242.552 145.321,240.27 147.064,238.527 149.157,238.527 150.408,239.778 150.408,243.123 149.572,243.96 145.983,243.96 145.289,243.266
VBUSN on Bottom Layer "Bottom Layer-VBUSN" (solid, remove dead copper, pour order 175): 123 vertices, not listed, extent 7.7,0.832 249.8,269.627
NetC5_2 on Bottom Layer "Bottom Layer-NetC5_2" (solid, pour order 170): 119.75,61.5 122,63.75 122,70.2 118.2,74 89.75,74 77.1,74 75.6,72.5 75.6,62.3 76.4,61.5 91.4,61.5
NetC6_2 on Bottom Layer "BOTTOM_LAYER_NETC6_2_P150" (solid, pour order 150): 87.9,36.6 90.8,39.5 119.75,39.5 122,37.25 122,17.1 118.4,13.5 98.4,13.5 87.9,24
EGND on Bottom Layer "BOTTOM_LAYER_NONET_P-001" (solid, pour order 158): 11.65,1.25 12.9,0 23.25,0 24.5,1.25 24.5,7.9 22.47,9.93 13.573,9.93 11.65,8.007
VN on Bottom Layer "BOTTOM_LAYER_VN_P157" (solid, pour order 157): 0.482,19.5 0.482,8.509 0.991,8 8.75,8 13.25,12.5 17.205,12.5 17.825,13.12 17.825,16.55 16.458,17.917 12.33,17.917 9.747,20.5 1.591,20.5 1.107,20.016
V_L3 on Bottom Layer "BOTTOM_LAYER_V_L3_P156" (solid, pour order 156): 0.482,42.75 0.482,25.018 1.5,24 10.161,24 13.5,27.339 13.5,41.732 11.232,44 1.733,44
V_L2 on Bottom Layer "BOTTOM_LAYER_V_L2_P155" (solid, pour order 155): 0.482,65.5 0.482,48.751 1.046,48.187 11.804,48.187 13.617,50 13.617,63.738 10.637,66.718 1.707,66.718
NetC2_2 on Bottom Layer "BOTTOM_LAYER_NETC2_2_P154" (solid, pour order 154): 30.503,56.257 30.503,41.832 32.335,40 68.75,40 71,42.25 71,56 69,58 32.489,58
NetC1_2 on Bottom Layer "BOTTOM_LAYER_NETC1_2_P153" (solid, pour order 153): 30.503,18.666 32.419,16.75 66.25,16.75 70,20.5 70,33.25 67.25,36 32.003,36 30.503,34.5
NetC3_2 on Bottom Layer "BOTTOM_LAYER_NETC3_2_P152" (solid, pour order 152): 30,79.5 30,63.55 31.55,62 66.25,62 69.5,65.25 69.5,73.25 61.507,81.243 31.743,81.243
V_L1 on Bottom Layer "BOTTOM_LAYER_V_L1_P151" (solid, pour order 151): 0.75,72.565 1.707,71.607 20.857,71.607 22.5,73.25 22.5,81.602 16.5,87.602 16.5,98.5 12.75,102.25 1.75,102.25 0.75,101.25 0.75,96
NetC4_2 on Bottom Layer "BOTTOM_LAYER_NETC4_2_P149" (solid, pour order 149): 84,55.8 85.7,57.5 119.75,57.5 122,55.25 122,45.375 120.125,43.5 85.1,43.5 84,44.6
V_C on Bottom Layer "BOTTOM_LAYER_V_C_P147" (solid, pour order 147): 25 vertices, not listed, extent 21.5,21.4 170,126.75
NetK1_1 on Bottom Layer "BOTTOM_LAYER_NETK1_1_P146" (solid, pour order 146): 159.25,72 159.25,64.75 161.25,62.75 186.75,62.75 187.75,63.75 187.75,71.5 184.75,74.5 161.75,74.5 160.75,73.5
V_A on Bottom Layer "BOTTOM_LAYER_V_A_P145" (solid, pour order 145): 85.5,111 85.5,101 92.5,94 129.75,94 147.25,76.5 183.53,76.5 188.069,81.039 188.069,85.931 184.25,89.75 154,89.75 146,97.75 146,107 137,116 90.5,116 86.25,111.75
NetK2_1 on Bottom Layer "BOTTOM_LAYER_NETK2_1_P144" (solid, pour order 144): 157.8,57.7 157.8,47.3 160.961,44.139 169.139,44.139 175.5,37.778 175.5,35.5 177.056,33.944 184.334,33.944 186.5,36.11 186.5,51.75 186.75,52 186.75,58.049 186.049,58.75 158.85,58.75
V_B on Bottom Layer "BOTTOM_LAYER_V_B_P143" (solid, pour order 143): 19 vertices, not listed, extent 151.25,38.016 229,111
V_B2 on Bottom Layer "Top Layer-NetL4_2" (solid, pour order 141): 151.5,157.5 154.456,154.544 177.508,154.544 183.047,160.083 183.047,165.153 183.047,174.322 182.868,174.5 163.454,174.5 160.45,171.496 153.475,171.496 151.5,169.521 151.5,160
QB_C on Bottom Layer "BOTTOM_LAYER_QB_C_P140" (solid, pour order 140): 25 vertices, not listed, extent 154.5,175.25 190.837,215.75
NetL4_2 on Bottom Layer "Top Layer-NetL4_2" (solid, pour order 139): 86,154 89.195,150.805 113.305,150.805 115.75,153.25 115.75,167.74 115.435,168.055 115.19,168.3 115.19,174.265 114.954,174.5 90.229,174.5 87.975,172.246 86,170.271 86,160.75
QA_C on Bottom Layer "Top Layer-QA_C" (solid, pour order 142): 25 vertices, not listed, extent 81.5,175.25 117.82,215.75
NetL7_2 on Bottom Layer "BOTTOM_LAYER_NETL7_2_P138" (solid, pour order 138): 41.722,174.75 29.103,174.75 17.65,174.75 16.4,173.5 16.4,156.35 23.75,149 45.5,149 50.136,153.636 50.136,165.519 48.655,167 43.225,167 42.085,168.14 42.085,174.389
QC_C on Bottom Layer "BOTTOM_LAYER_QC_C_P137" (solid, pour order 137): 27 vertices, not listed, extent 0.75,175.25 44.932,215.75
GND_GATEB on Bottom Layer "Bottom Layer-GND_GATEB" (solid, pour order 130): 39 vertices, not listed, extent 186,182.297 224.5,228.065
VBUSN on Bottom Layer "BOTTOM_LAYER_NONET_P-001" (solid, pour order 117): 81,208.5 82.25,209.75 82.25,216.25 82.725,216.725 82.725,217.675 82.2,218.2 71.107,218.2 70.624,217.717 70.624,209.441 71.565,208.5
VBUSN on Bottom Layer "BOTTOM_LAYER_NONET_P-001" (solid, pour order 116): 153.75,215.845 153.75,211.041 152.15,209.441 146.631,209.441 143.45,212.622 143.45,215.31 144.751,216.611 152.747,216.611
VBUSM on Bottom Layer "BOTTOM_LAYER_NONET_P-001" (solid, pour order 115): 117.276,213.075 117.276,217.026 118.25,218 127.479,218 127.689,217.79 127.689,213.219 126.7,212.23 118.12,212.23
VBUSM on Bottom Layer "BOTTOM_LAYER_NONET_P-001" (solid, pour order 114): 44.401,217.25 44.401,213.277 45.448,212.23 58.927,212.23 61.75,215.053 61.75,220.021 60.938,220.833 47.984,220.833
GND_ACSensing on Bottom Layer "BOTTOM_LAYER_NONET_P-001" (solid, pour order 112): 237.999,219.987 237.999,212.115 239.333,210.781 242.865,210.781 244.65,212.566 244.65,219.973 244.432,220.191 238.126,220.191
GND_GATEA on Bottom Layer "Bottom Layer-GND_GATEA" (solid, pour order 9): 24 vertices, not listed, extent 113,182.414 124.145,220.148
VBUSM on Bottom Layer "BOTTOM_LAYER_VBUSM_P069" (solid, remove dead copper, pour order 69): 215.495,209.909 214.631,209.045 214.631,199.558 216.232,197.957 217.284,196.905 217.284,187.14 217.77,186.654 224.139,186.654 224.702,187.217 224.702,198.988 224.714,199 224.101,199.613 224.101,201.51 224.101,209.258 223.45,209.909
GND_GATEC on Bottom Layer "BOTTOM_LAYER_GND_GATEC_P068" (solid, pour order 68): 21 vertices, not listed, extent 232.45,188.534 243.757,210
GND_GATEA on Bottom Layer "BOTTOM_LAYER_GND_GATEA_P066" (solid, pour order 66): 18 vertices, not listed, extent 226.513,187.404 234.122,210
VBUSM on Bottom Layer "BOTTOM_LAYER_VBUSM_P065" (solid, pour order 65): 143.173,192.171 143.991,191.353 150.681,191.353 152.191,192.863 152.191,197.527 150.643,199.075 143.507,199.075 143.173,198.741
VBUSP on Bottom Layer "Bottom Layer-VBUSP" (solid, pour order 53): 33 vertices, not listed, extent 29.5,208.297 183.5,240.927
VBUSN on Bottom Layer "BOTTOM_LAYER_VBUSN_P049" (solid, pour order 49): 17 vertices, not listed, extent 127.139,177.178 143.45,206.305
